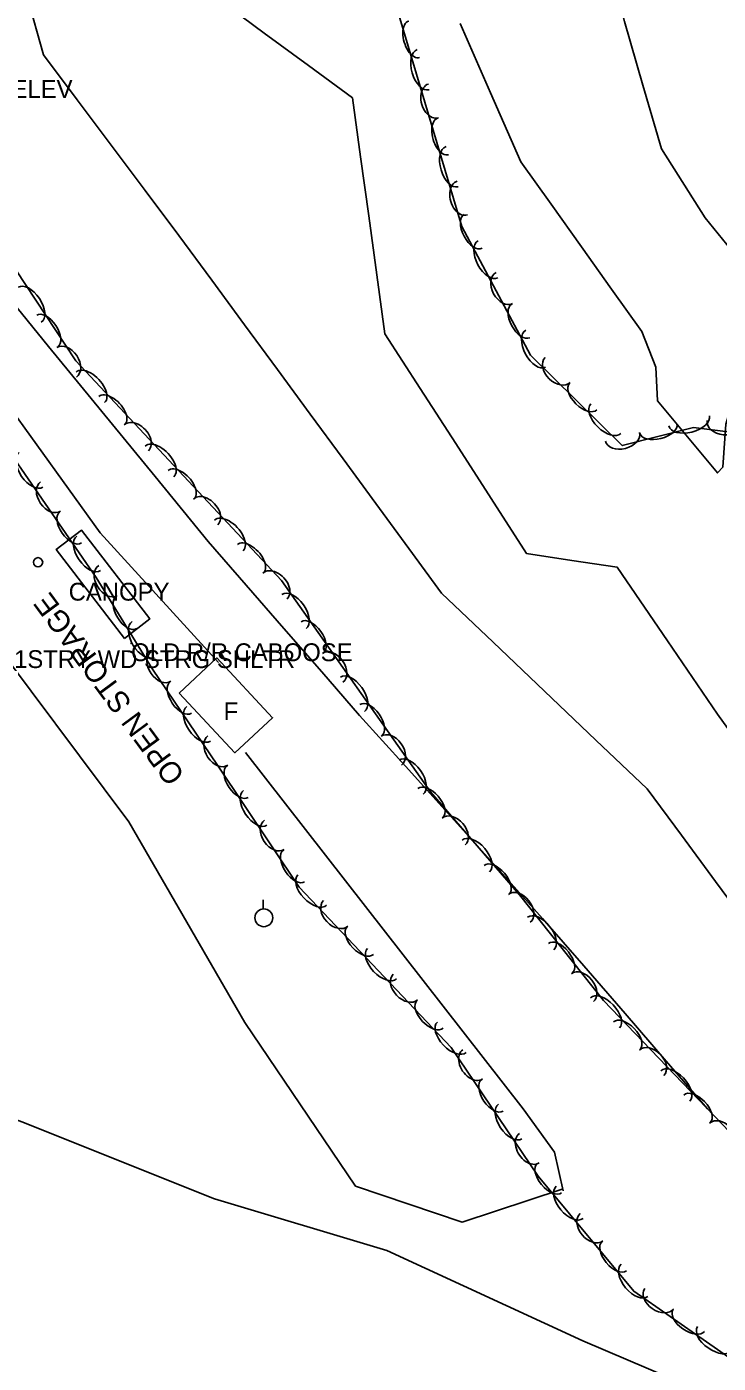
# Model space of a CAD drawing. Extents: x 1451369 to 1458940, y 1868647 to 1875095.
# Drawn here: x 1454358 to 1454551.8, y 1871083.8 to 1871458.6 of the extents above; entities that cross this region are included whole.
import ezdxf

# ---------------------------------------------------------------- set-up
doc = ezdxf.new("R2010")
doc.units = 0
for name, color, linetype in [('E_Const Align', 7, 'Continuous'), ('E_Property Line', 7, 'Continuous'), ('E_Proposed ROW and Easements', 7, 'Continuous'), ('E_ROW Point Number', 7, 'Continuous'), ('E_Tract Residual', 7, 'Continuous'), ('S_BUILDING_ANNOT', 7, 'Continuous'), ('S_EXIST_ROW', 7, 'Continuous'), ('S_MISC_BOUNDARY', 7, 'Continuous'), ('S_MISC_BOUNDARY_ANNOT', 7, 'Continuous'), ('S_SECONDARY_CTL_ANNOT', 7, 'Continuous'), ('S_SURVEY_TEXT_ANNOT', 7, 'Continuous'), ('S_TRAILS', 7, 'Continuous')]:
    doc.layers.add(name, color=color, linetype=linetype)

msp = doc.modelspace()

# ---------------------------------------------------------------- linework, layer by layer
at = {"layer": 'E_Const Align'}
msp.add_line((1454424.31, 1871211.24), (1454424.31, 1871213.72), dxfattribs=at)
for centre, radius in [((1454361.19, 1871308.4), 1.31), ((1454424.46, 1871208.72), 2.5)]:
    msp.add_circle(centre, radius, dxfattribs=at)
at = {"layer": 'E_Property Line'}
for points in [[(1454385.38, 1871287.08), (1454366.23, 1871311.99), (1454373.34, 1871317.46), (1454392.49, 1871292.54)], [(1454400.75, 1871271.74), (1454416.37, 1871254.98), (1454426.91, 1871264.8), (1454411.29, 1871281.57)]]:
    msp.add_lwpolyline(points, close=True, dxfattribs=at)
at = {"layer": 'E_Proposed ROW and Easements'}
msp.add_lwpolyline([(1454387.29, 1871285.68), (1454387.29, 1871285.73), (1454387.29, 1871285.68), (1454387.24, 1871285.68), (1454387.29, 1871285.68), (1454387.29, 1871285.63), (1454387.29, 1871285.68), (1454387.34, 1871285.68)], dxfattribs=at)
at = {"layer": 'E_ROW Point Number'}
for points in [[(1454769.59, 1871085.19), (1454734.6, 1871121.15), (1454698.54, 1871159), (1454682.97, 1871178.23), (1454631.67, 1871234.64), (1454607.53, 1871257.1), (1454578.57, 1871284.24), (1454566.94, 1871304.77), (1454571.82, 1871327.97), (1454565.11, 1871343.72), (1454544.85, 1871346.2), (1454524.89, 1871341.15), (1454499.19, 1871366.49), (1454479.99, 1871402.54), (1454460.24, 1871468.96)], [(1454354.98, 1871390.38), (1454371.8, 1871364.92), (1454429.4, 1871303.3), (1454471.21, 1871244.05), (1454496.14, 1871215.11), (1454519.64, 1871185.53), (1454557.32, 1871146.28), (1454583.57, 1871119.27), (1454622.38, 1871070.6), (1454661.94, 1871037.28), (1454703.33, 1871008.9), (1454731.19, 1870986.38), (1454759.84, 1870960.63)], [(1454686.82, 1870930.03), (1454660.52, 1870951.37), (1454644.8, 1870974.62), (1454621.9, 1871011.26), (1454608.54, 1871028.34), (1454594.8, 1871054.46), (1454558.65, 1871082.65), (1454528.1, 1871103.96), (1454501.29, 1871136.27), (1454476.93, 1871172.33), (1454434.4, 1871217.27), (1454411.48, 1871251.51), (1454393.25, 1871278.48), (1454377.48, 1871304.11), (1454353.64, 1871338.7)]]:
    msp.add_lwpolyline(points, dxfattribs=at)
for centre, major_axis, ratio, start_param, end_param in [((1454466.58, 1871455.06), (1.52, -5.12), 0.541221, 3.14215, 6.283743), ((1454469.11, 1871446.57), (1.67, -5.62), 0.550611, 3.142169, 6.283761), ((1454472, 1871437.78), (1.41, -4.75), 0.685972, 3.142537, 6.28413), ((1454474.68, 1871427.84), (1.52, -5.12), 0.541221, 3.14215, 6.283743), ((1454477.21, 1871419.35), (1.67, -5.62), 0.550611, 3.142169, 6.283761), ((1454480.09, 1871410.56), (1.41, -4.75), 0.685972, 3.142537, 6.28413), ((1454483.11, 1871401.21), (2.51, -4.72), 0.540637, 3.141593, 6.283185), ((1454487.27, 1871393.38), (2.76, -5.18), 0.550016, 3.141593, 6.283185), ((1454491.86, 1871385.33), (2.33, -4.37), 0.685231, 3.141593, 6.283185), ((1454358.88, 1871380.63), (-3.23, 4.9), 0.549956, 3.141593, 6.283185), ((1454496.47, 1871376.12), (2.51, -4.72), 0.540637, 3.141593, 6.283185), ((1454363.77, 1871373.23), (-2.95, 4.46), 0.540578, 3.141593, 6.283185), ((1454500.64, 1871368.29), (2.76, -5.18), 0.550016, 3.141593, 6.283185), ((1454369.23, 1871364.49), (-2.73, 4.14), 0.685157, 3.141593, 6.283185), ((1454506.81, 1871362.32), (3.53, -3.48), 0.685249, 3.141593, 6.283185), ((1454375.85, 1871357.48), (-4.01, 4.29), 0.549956, 3.141518, 6.283111), ((1454513.96, 1871354.91), (3.81, -3.75), 0.540651, 3.141593, 6.283185), ((1454381.9, 1871351), (-3.65, 3.91), 0.540577, 3.14152, 6.283113), ((1454520.28, 1871348.68), (4.18, -4.12), 0.55003, 3.141593, 6.283185), ((1454388.75, 1871343.3), (-3.38, 3.62), 0.685156, 3.14147, 6.283063), ((1454535.02, 1871345.9), (5.18, 1.31), 0.540699, 3.141593, 6.283185), ((1454543.62, 1871348.07), (5.69, 1.44), 0.55008, 3.141593, 6.283185), ((1454553.6, 1871347.53), (4.92, -0.6), 0.685299, 3.141593, 6.283185), ((1454524.97, 1871343.63), (4.8, 1.22), 0.685311, 3.141593, 6.283185), ((1454359.24, 1871334.33), (3.33, -4.83), 0.549955, 3.141593, 6.283185), ((1454395.26, 1871336.71), (-4.01, 4.29), 0.549956, 3.141518, 6.283111), ((1454401.32, 1871330.23), (-3.65, 3.91), 0.540577, 3.14152, 6.283113), ((1454364.7, 1871326.85), (2.81, -4.08), 0.685155, 3.141593, 6.283185), ((1454408.16, 1871322.53), (-3.38, 3.62), 0.685156, 3.14147, 6.283063), ((1454370.34, 1871318.22), (3.03, -4.4), 0.540577, 3.141593, 6.283185), ((1454414.67, 1871315.94), (-4.01, 4.29), 0.549956, 3.141518, 6.283111), ((1454375.37, 1871310.92), (3.33, -4.83), 0.549955, 3.141593, 6.283185), ((1454420.73, 1871309.47), (-3.65, 3.91), 0.540577, 3.14152, 6.283113), ((1454380.8, 1871303.27), (2.6, -4.22), 0.685159, 3.141593, 6.283185), ((1454427.57, 1871301.76), (-3.38, 3.62), 0.685156, 3.14147, 6.283063), ((1454385.97, 1871294.36), (2.8, -4.55), 0.54058, 3.141593, 6.283185), ((1454432.93, 1871294.61), (-3.38, 4.79), 0.549954, 3.141593, 6.283185), ((1454390.62, 1871286.8), (3.07, -5), 0.549958, 3.141593, 6.283185), ((1454438.05, 1871287.37), (-3.08, 4.37), 0.540576, 3.141593, 6.283185), ((1454395.67, 1871279.16), (2.78, -4.11), 0.685156, 3.141593, 6.283185), ((1454443.77, 1871278.8), (-2.86, 4.05), 0.685155, 3.141593, 6.283185), ((1454449.32, 1871271.39), (-3.38, 4.79), 0.549954, 3.141593, 6.283185), ((1454401.22, 1871270.48), (2.99, -4.43), 0.540577, 3.141593, 6.283185), ((1454406.19, 1871263.13), (3.29, -4.86), 0.549955, 3.141593, 6.283185), ((1454454.44, 1871264.14), (-3.08, 4.37), 0.540576, 3.141593, 6.283185), ((1454460.17, 1871255.57), (-2.86, 4.05), 0.685155, 3.141593, 6.283185), ((1454411.59, 1871255.61), (2.78, -4.11), 0.685156, 3.141593, 6.283185), ((1454465.72, 1871248.16), (-3.38, 4.79), 0.549954, 3.141593, 6.283185), ((1454417.12, 1871246.9), (2.97, -4.44), 0.540577, 3.141593, 6.283185), ((1454471.13, 1871240.89), (-3.49, 4.05), 0.540573, 3.141593, 6.283185), ((1454422.05, 1871239.53), (3.26, -4.88), 0.549956, 3.141593, 6.283185), ((1454477.66, 1871232.92), (-3.23, 3.76), 0.68515, 3.141593, 6.283185), ((1454427.42, 1871231.98), (2.76, -4.12), 0.685156, 3.141593, 6.283185), ((1454483.9, 1871226.07), (-3.83, 4.45), 0.549951, 3.141593, 6.283185), ((1454432.93, 1871223.27), (2.97, -4.44), 0.540577, 3.141593, 6.283185), ((1454489.69, 1871219.35), (-3.49, 4.05), 0.540573, 3.141593, 6.283185), ((1454438.04, 1871216.5), (4.03, -4.26), 0.54995, 3.141593, 6.283185), ((1454496.06, 1871211.37), (-3.08, 3.88), 0.685152, 3.141593, 6.283185), ((1454444.6, 1871209.96), (3.41, -3.6), 0.685149, 3.141593, 6.283185), ((1454502.03, 1871204.29), (-3.65, 4.59), 0.549952, 3.141593, 6.283185), ((1454451.49, 1871202.3), (3.67, -3.88), 0.540572, 3.141593, 6.283185), ((1454507.54, 1871197.35), (-3.33, 4.19), 0.540574, 3.141593, 6.283185), ((1454457.58, 1871195.86), (4.03, -4.26), 0.54995, 3.141593, 6.283185), ((1454464.14, 1871189.31), (3.41, -3.6), 0.685149, 3.141593, 6.283185), ((1454513.75, 1871189.12), (-3.08, 3.88), 0.685152, 3.141593, 6.283185), ((1454471.03, 1871181.65), (3.67, -3.88), 0.540572, 3.141593, 6.283185), ((1454520.04, 1871182.05), (-4.06, 4.23), 0.54995, 3.141593, 6.283185), ((1454477.12, 1871175.21), (4.03, -4.26), 0.54995, 3.141593, 6.283185), ((1454526.18, 1871175.66), (-3.7, 3.86), 0.540572, 3.141593, 6.283185), ((1454482.99, 1871167.62), (2.77, -4.1), 0.685863, 3.140342, 6.281935), ((1454533.13, 1871168.04), (-3.43, 3.57), 0.685149, 3.141593, 6.283185), ((1454539.73, 1871161.55), (-4.06, 4.23), 0.54995, 3.141593, 6.283185), ((1454488.53, 1871158.94), (2.99, -4.42), 0.541135, 3.140854, 6.282446), ((1454545.87, 1871155.15), (-3.7, 3.86), 0.540572, 3.141593, 6.283185), ((1454493.49, 1871151.6), (3.28, -4.86), 0.550523, 3.14083, 6.282422), ((1454552.82, 1871147.54), (-3.43, 3.57), 0.685149, 3.141593, 6.283185), ((1454498.88, 1871144.08), (2.77, -4.1), 0.685863, 3.140342, 6.281935), ((1454504.5, 1871135.72), (3.41, -4.11), 0.540573, 3.141593, 6.283185), ((1454510.16, 1871128.9), (3.75, -4.52), 0.549952, 3.141593, 6.283185), ((1454516.28, 1871121.94), (3.16, -3.81), 0.685151, 3.141593, 6.283185), ((1454522.65, 1871113.85), (3.41, -4.11), 0.540573, 3.141593, 6.283185), ((1454528.32, 1871107.02), (3.75, -4.52), 0.549952, 3.141593, 6.283185), ((1454535.24, 1871101.89), (4.06, -2.84), 0.685153, 3.141593, 6.283185), ((1454543.54, 1871095.78), (4.39, -3.06), 0.540575, 3.141593, 6.283185), ((1454550.81, 1871090.71), (4.81, -3.36), 0.549953, 3.141593, 6.283185)]:
    msp.add_ellipse(centre, major_axis=major_axis, ratio=ratio, start_param=start_param, end_param=end_param, dxfattribs=at)
at = {"layer": 'E_Tract Residual'}
for points in [[(1454284.21, 1871464.5), (1454293.3, 1871455.74), (1454302.39, 1871446.97), (1454309.79, 1871433.77), (1454317.19, 1871420.58), (1454333.21, 1871403.87), (1454349.24, 1871387.16), (1454364.16, 1871368.92), (1454379.07, 1871350.69), (1454393.99, 1871332.45), (1454408.91, 1871314.21), (1454419.51, 1871302.02), (1454430.1, 1871289.83), (1454440.7, 1871277.65), (1454451.3, 1871265.46), (1454464.12, 1871251.23), (1454476.93, 1871237), (1454489.75, 1871222.77), (1454502.57, 1871208.55), (1454514.12, 1871195.2), (1454525.67, 1871181.84), (1454537.22, 1871168.49), (1454548.77, 1871155.14)], [(1454479.45, 1871459.48), (1454487.96, 1871440.08), (1454496.47, 1871420.69), (1454504.96, 1871408.8), (1454513.44, 1871396.91), (1454521.92, 1871385.02), (1454530.41, 1871373.12), (1454534.3, 1871363.17), (1454534.74, 1871353.7), (1454543.14, 1871343.58), (1454551.55, 1871333.45), (1454553.08, 1871335.1), (1454553.96, 1871347.1), (1454558.84, 1871363.47), (1454562.32, 1871383.14), (1454563.1, 1871386.17), (1454565.32, 1871385.29), (1454571.29, 1871378.9), (1454583.47, 1871366.9)]]:
    msp.add_lwpolyline(points, dxfattribs=at)
at = {"layer": 'S_EXIST_ROW'}
for points in [[(1454562.7, 1871387.08), (1454548.13, 1871404.98), (1454535.85, 1871424.34), (1454530.7, 1871442.21), (1454525.54, 1871460.07), (1454519.63, 1871483.17), (1454512.82, 1871496.11)], [(1454560.6, 1871205.86), (1454551.04, 1871218.85), (1454541.48, 1871231.84), (1454531.92, 1871244.83), (1454517.52, 1871258.57), (1454503.11, 1871272.31), (1454488.7, 1871286.05), (1454474.29, 1871299.79), (1454465.09, 1871312.32), (1454455.89, 1871324.85), (1454446.69, 1871337.38), (1454437.49, 1871349.91), (1454428.29, 1871362.43), (1454419.09, 1871374.96), (1454409.88, 1871387.49), (1454400.68, 1871400.02), (1454391.19, 1871412.7), (1454381.69, 1871425.39), (1454372.2, 1871438.08), (1454362.7, 1871450.76), (1454358.17, 1871467.08)], [(1454669.39, 1871148.22), (1454651.32, 1871161.85), (1454633.26, 1871175.48), (1454615.19, 1871189.12), (1454597.13, 1871202.75), (1454585.74, 1871218.51), (1454574.36, 1871234.27), (1454562.98, 1871250.04), (1454551.59, 1871265.8), (1454537.54, 1871286.41), (1454523.49, 1871307.02), (1454510.77, 1871308.95), (1454498.06, 1871310.88), (1454488.14, 1871326.29), (1454478.22, 1871341.7), (1454468.29, 1871357.11), (1454458.37, 1871372.52), (1454456.11, 1871389.06), (1454453.85, 1871405.59), (1454451.59, 1871422.12), (1454449.33, 1871438.65), (1454436.97, 1871447.74), (1454424.6, 1871456.83), (1454412.24, 1871465.92)]]:
    msp.add_lwpolyline(points, dxfattribs=at)
at = {"layer": 'S_MISC_BOUNDARY'}
for points in [[(1454508.04, 1871132.59), (1454480.07, 1871123.31), (1454450.16, 1871133.48), (1454419.11, 1871179.34), (1454386.64, 1871235.64), (1454345.34, 1871290.82), (1454325.41, 1871316.62), (1454288.53, 1871360.43), (1454279.55, 1871373.71), (1454281.02, 1871384.44), (1454292.69, 1871389.73), (1454300.28, 1871390.19), (1454342.99, 1871366.06), (1454378.58, 1871316.67), (1454411.72, 1871280.3)], [(1454419.35, 1871255.05), (1454497.13, 1871155.1), (1454505.94, 1871143), (1454508.32, 1871132.18)]]:
    msp.add_lwpolyline(points, dxfattribs=at)
at = {"layer": 'S_TRAILS'}
msp.add_lwpolyline([(1454664.78, 1870924.54), (1454627.15, 1870976.01), (1454610.41, 1871007.49), (1454602.85, 1871037.26), (1454596.2, 1871048.11), (1454587.59, 1871056.55), (1454556.97, 1871071.66), (1454513.83, 1871090.1), (1454458.91, 1871115.43), (1454410.66, 1871129.87), (1454356.65, 1871151.49), (1454269.77, 1871183.68), (1454217.81, 1871202.95), (1454169.41, 1871220.7), (1454122.52, 1871231.37), (1454082.04, 1871238.71), (1454064.72, 1871238.64)], dxfattribs=at)

# ---------------------------------------------------------------- texts
at = {"layer": 'S_BUILDING_ANNOT'}
for s, height, p in [('CANOPY', 5.001, (1454369.78, 1871297.66)), ('F', 5, (1454413.19, 1871264.14))]:
    msp.add_text(s, height=height, dxfattribs=at).set_placement(p)
at = {"layer": 'S_MISC_BOUNDARY_ANNOT'}
msp.add_text('OPEN STORAGE', height=6.0005, rotation=126.4391, dxfattribs=at).set_placement((1454402.55, 1871248.77))
at = {"layer": 'S_SECONDARY_CTL_ANNOT'}
msp.add_text('PD:8 SPIKE TRIG ELEV', height=5, dxfattribs=at).set_placement((1454297.65, 1871438.62))
at = {"layer": 'S_SURVEY_TEXT_ANNOT'}
for s, p in [('1STRY WD STRG SHLTR', (1454354.48, 1871278.75)), ('OLD R/R CABOOSE', (1454387.29, 1871280.68))]:
    msp.add_text(s, height=5, dxfattribs=at).set_placement(p)

doc.saveas('drawing.dxf')
